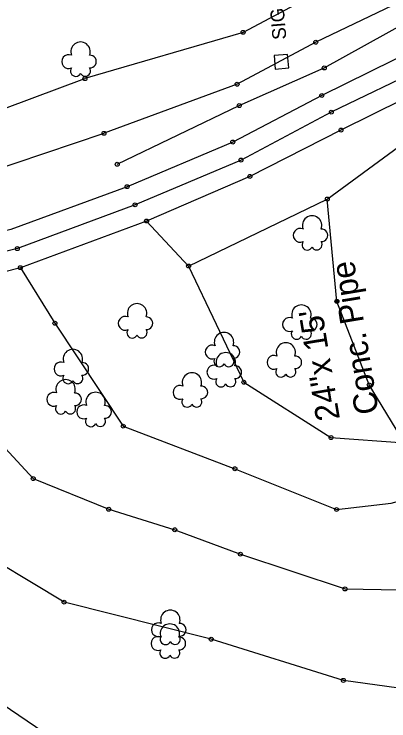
# Model space of a CAD drawing. Extents: x 21481721 to 21494985, y 8063982 to 8084842.
# Drawn here: x 21487944.9 to 21488039.9, y 8075079.6 to 8075258.6 of the extents above; entities that cross this region are included whole.
import ezdxf

# ---------------------------------------------------------------- set-up
doc = ezdxf.new("R2010")
doc.units = 0
for name, color, linetype in [('EXT_BL', 7, 'Continuous'), ('EXT_C', 7, 'Continuous'), ('EXT_D', 7, 'Continuous'), ('EXT_EP', 7, 'Continuous'), ('SurNaturalCells', 7, 'Continuous'), ('SurRoadPoints', 7, 'Continuous'), ('SurSurveyPoints', 7, 'Continuous'), ('Text', 7, 'Continuous')]:
    doc.layers.add(name, color=color, linetype=linetype)

msp = doc.modelspace()

# ---------------------------------------------------------------- linework, layer by layer
at = {"layer": 'EXT_BL'}
for points in [[(21488039.84, 8075278.16), (21488024.08, 8075265.27), (21488002.96, 8075254.02), (21487962.88, 8075242.3)], [(21488063.52, 8075272.91), (21488053.64, 8075266.28), (21488040.85, 8075260.85), (21488021.38, 8075251.52), (21488001.44, 8075240.87), (21487967.71, 8075228.44)], [(21487989.15, 8075194.82), (21488024.32, 8075211.79), (21488042.4, 8075224.99), (21488060.17, 8075236.75), (21488082.71, 8075245.46), (21488091.82, 8075246.21), (21488104.06, 8075246.76), (21488113.72, 8075247.16), (21488125.22, 8075247.74), (21488135.81, 8075248.16), (21488149.96, 8075248.91), (21488158.85, 8075244.75)], [(21487805.81, 8075200.57), (21487843.69, 8075208.86), (21487881.33, 8075216.99), (21487907.27, 8075223.5), (21487936.1, 8075232.4), (21487962.88, 8075242.3)], [(21487807.01, 8075190.56), (21487845.36, 8075196.81), (21487882.48, 8075203.41), (21487908.34, 8075208.9), (21487937.56, 8075218.37), (21487967.71, 8075228.44)], [(21488043.85, 8075149.99), (21488034.94, 8075164.72), (21488026.75, 8075185.86), (21488024.32, 8075211.79)], [(21487978.49, 8075206.22), (21487989.15, 8075194.82), (21488003.15, 8075165.37), (21488025.25, 8075151.37), (21488043.85, 8075149.99), (21488056, 8075154.9)], [(21487946.5, 8075194.4), (21487955.26, 8075180.32), (21487972.57, 8075154.25), (21488000.89, 8075143.46), (21488026.66, 8075133.14), (21488040.5, 8075134.78), (21488063.33, 8075140.96)], [(21487912.64, 8075185.75), (21487921.08, 8075171.87), (21487949.76, 8075140.97), (21487968.9, 8075133.2), (21487985.64, 8075128.01), (21488002.28, 8075121.82), (21488028.81, 8075113.01), (21488056.18, 8075112.57), (21488095.4, 8075114.28)], [(21488096.33, 8075080.43), (21488058.31, 8075085.68), (21488028.39, 8075089.85), (21487994.89, 8075100.27), (21487957.6, 8075109.66), (21487932.27, 8075124.86), (21487903.55, 8075143.43), (21487883.81, 8075170.57), (21487884.18, 8075181.16)], [(21488104.12, 8075053.16), (21488060.1, 8075057.21), (21488026.96, 8075060.99), (21487993.7, 8075067.26), (21487956.42, 8075073.93), (21487921.18, 8075097.88), (21487878.26, 8075124.79), (21487850.62, 8075156.33), (21487846.7, 8075177.74)]]:
    msp.add_lwpolyline(points, dxfattribs=at)
at = {"layer": 'EXT_C'}
for points in [[(21488076.14, 8075256.92), (21488049.24, 8075245.29), (21488025.33, 8075233.8), (21488002.44, 8075221.66), (21487975.58, 8075210.32)], [(21487975.58, 8075210.32), (21487945.74, 8075199.23), (21487911.38, 8075190.53), (21487884.07, 8075186.14), (21487846.99, 8075182.8), (21487808.32, 8075180.06)]]:
    msp.add_lwpolyline(points, dxfattribs=at)
at = {"layer": 'EXT_D'}
msp.add_lwpolyline([(21487971.05, 8075220.59), (21488002, 8075235.48), (21488023.55, 8075245), (21488044.71, 8075256.74), (21488066.12, 8075263.19), (21488069.65, 8075264.54)], dxfattribs=at)
at = {"layer": 'EXT_EP'}
for points in [[(21488074.68, 8075261.58), (21488095.95, 8075269.14), (21488109.99, 8075271.51), (21488127.42, 8075272.46), (21488140.89, 8075272.69), (21488148.98, 8075272.17), (21488140.89, 8075272.69), (21488127.42, 8075272.46), (21488109.99, 8075271.51), (21488095.95, 8075269.14), (21488074.68, 8075261.58), (21488047.08, 8075249.97), (21488022.91, 8075238.02), (21488000.35, 8075226.23), (21487973.56, 8075214.92)], [(21488077.75, 8075252.32), (21488051.49, 8075241.01), (21488027.78, 8075229.25), (21488004.69, 8075217.52), (21487978.49, 8075206.22)], [(21487973.56, 8075214.92), (21487944.1, 8075204.06), (21487909.77, 8075195.4), (21487882.83, 8075190.99), (21487845.98, 8075187.82), (21487807.65, 8075185.24)], [(21487978.49, 8075206.22), (21487946.5, 8075194.4), (21487912.64, 8075185.75), (21487884.18, 8075181.16), (21487846.7, 8075177.74), (21487809.68, 8075175.41)]]:
    msp.add_lwpolyline(points, dxfattribs=at)
at = {"layer": 'SurNaturalCells'}
for centre, radius, start, end in [((21487961.77, 8075249.12), 2.46, 338.2051, 201.7949), ((21487958.75, 8075246.61), 1.76, 65.4824, 294.5175), ((21487964.16, 8075246.61), 1.6, 265.9982, 94.0018), ((21487960.55, 8075244.2), 1.34, 142.7501, 335.3223), ((21487962.96, 8075244.23), 1.34, 206.5242, 35.4033), ((21488020.45, 8075205.11), 2.46, 338.2051, 201.7949), ((21488017.44, 8075202.6), 1.76, 65.4824, 294.5175), ((21488022.85, 8075202.6), 1.6, 265.9982, 94.0018), ((21488019.24, 8075200.19), 1.34, 142.7501, 335.3223), ((21488021.65, 8075200.23), 1.34, 206.5242, 35.4033), ((21487976.08, 8075182.83), 2.46, 338.2051, 201.7949), ((21488017.74, 8075182.51), 2.46, 338.2051, 201.7949), ((21487973.07, 8075180.31), 1.76, 65.4824, 294.5175), ((21487978.47, 8075180.31), 1.6, 265.9982, 94.0018), ((21488014.72, 8075180), 1.76, 65.4824, 294.5175), ((21488020.13, 8075180), 1.6, 265.9982, 94.0018), ((21487974.86, 8075177.9), 1.34, 142.7501, 335.3223), ((21487977.27, 8075177.94), 1.34, 206.5242, 35.4033), ((21488016.52, 8075177.59), 1.34, 142.7501, 335.3223), ((21488018.93, 8075177.62), 1.34, 206.5242, 35.4033), ((21487998.13, 8075175.54), 2.46, 338.2051, 201.7949), ((21488013.8, 8075172.93), 2.46, 338.2051, 201.7949), ((21487959.81, 8075171.26), 2.46, 338.2051, 201.7949), ((21487995.12, 8075173.03), 1.76, 65.4824, 294.5175), ((21488000.53, 8075173.03), 1.6, 265.9982, 94.0018), ((21487996.92, 8075170.62), 1.34, 142.7501, 335.3223), ((21487998.58, 8075170.44), 2.46, 338.2051, 201.7949), ((21487999.33, 8075170.66), 1.34, 206.5242, 35.4033), ((21488010.79, 8075170.42), 1.76, 65.4824, 294.5175), ((21488016.2, 8075170.42), 1.6, 265.9982, 94.0018), ((21487956.8, 8075168.75), 1.76, 65.4824, 294.5175), ((21487962.21, 8075168.75), 1.6, 265.9982, 94.0018), ((21487995.57, 8075167.93), 1.76, 65.4824, 294.5175), ((21488000.98, 8075167.93), 1.6, 265.9982, 94.0018), ((21487990, 8075165.32), 2.46, 338.2051, 201.7949), ((21488012.58, 8075168.01), 1.34, 142.7501, 335.3223), ((21488015, 8075168.04), 1.34, 206.5242, 35.4033), ((21487957.98, 8075163.57), 2.46, 338.2051, 201.7949), ((21487958.6, 8075166.34), 1.34, 142.7501, 335.3223), ((21487961.01, 8075166.37), 1.34, 206.5242, 35.4033), ((21487997.36, 8075165.52), 1.34, 142.7501, 335.3223), ((21487999.78, 8075165.56), 1.34, 206.5242, 35.4033), ((21487986.98, 8075162.81), 1.76, 65.4824, 294.5175), ((21487992.39, 8075162.81), 1.6, 265.9982, 94.0018), ((21487954.97, 8075161.05), 1.76, 65.4824, 294.5175), ((21487960.38, 8075161.05), 1.6, 265.9982, 94.0018), ((21487965.57, 8075160.39), 2.46, 338.2051, 201.7949), ((21487988.78, 8075160.4), 1.34, 142.7501, 335.3223), ((21487991.19, 8075160.43), 1.34, 206.5242, 35.4033), ((21487956.77, 8075158.64), 1.34, 142.7501, 335.3223), ((21487959.18, 8075158.68), 1.34, 206.5242, 35.4033), ((21487962.56, 8075157.87), 1.76, 65.4824, 294.5175), ((21487967.97, 8075157.87), 1.6, 265.9982, 94.0018), ((21487964.35, 8075155.46), 1.34, 142.7501, 335.3223), ((21487966.77, 8075155.5), 1.34, 206.5242, 35.4033), ((21487984.52, 8075105.17), 2.46, 338.2051, 201.7949), ((21487981.5, 8075102.66), 1.76, 65.4824, 294.5175), ((21487984.4, 8075101.7), 2.46, 338.2051, 201.7949), ((21487986.91, 8075102.66), 1.6, 265.9982, 94.0018), ((21487981.39, 8075099.19), 1.76, 65.4824, 294.5175), ((21487983.3, 8075100.25), 1.34, 142.7501, 335.3223), ((21487985.71, 8075100.29), 1.34, 206.5242, 35.4033), ((21487986.8, 8075099.19), 1.6, 265.9982, 94.0018), ((21487983.19, 8075096.78), 1.34, 142.7501, 335.3223), ((21487985.6, 8075096.82), 1.34, 206.5242, 35.4033)]:
    msp.add_arc(centre, radius, start, end, dxfattribs=at)
at = {"layer": 'SurRoadPoints'}
msp.add_lwpolyline([(21488014.38, 8075246.72), (21488014.38, 8075246.72), (21488014.24, 8075248.42), (21488010.82, 8075248.13), (21488011.11, 8075244.72), (21488014.52, 8075245.01), (21488014.38, 8075246.71)], dxfattribs=at)
at = {"layer": 'SurSurveyPoints'}
for centre in [(21488002.96, 8075254.02), (21488021.38, 8075251.52), (21488023.55, 8075245), (21487962.88, 8075242.3), (21487962.88, 8075242.3), (21488001.44, 8075240.87), (21488022.91, 8075238.02), (21488002, 8075235.48), (21488025.33, 8075233.8), (21487967.71, 8075228.44), (21487967.71, 8075228.44), (21488027.78, 8075229.25), (21488000.35, 8075226.23), (21488002.44, 8075221.66), (21487971.05, 8075220.59), (21488004.69, 8075217.52), (21487973.56, 8075214.92), (21487973.56, 8075214.92), (21487975.58, 8075210.32), (21487975.58, 8075210.32), (21488024.32, 8075211.79), (21488024.32, 8075211.79), (21487978.49, 8075206.22), (21487978.49, 8075206.22), (21487978.49, 8075206.22), (21487945.74, 8075199.23), (21487946.5, 8075194.4), (21487946.5, 8075194.4), (21487989.15, 8075194.82), (21487989.15, 8075194.82), (21488026.75, 8075185.86), (21487955.26, 8075180.32), (21488003.15, 8075165.37), (21488034.94, 8075164.72), (21487972.57, 8075154.25), (21488025.25, 8075151.37), (21488000.89, 8075143.46), (21487949.76, 8075140.97), (21487968.9, 8075133.2), (21488026.66, 8075133.14), (21487985.64, 8075128.01), (21488002.28, 8075121.82), (21488028.81, 8075113.01), (21487957.6, 8075109.66), (21487994.89, 8075100.27), (21488028.39, 8075089.85)]:
    msp.add_circle(centre, 0.5, dxfattribs=at)

# ---------------------------------------------------------------- texts
at = {"layer": 'SurRoadPoints'}
msp.add_text('SIGN', height=3.498, rotation=94.8055, dxfattribs=at).set_placement((21488013.95, 8075252.3))
at = {"layer": 'Text'}
for s, p in [('Conc. Pipe', (21488037.39, 8075157.73)), ('24"x 15\'', (21488027.53, 8075156.11))]:
    msp.add_text(s, height=6, rotation=99.3211, dxfattribs=at).set_placement(p)

doc.saveas('drawing.dxf')
